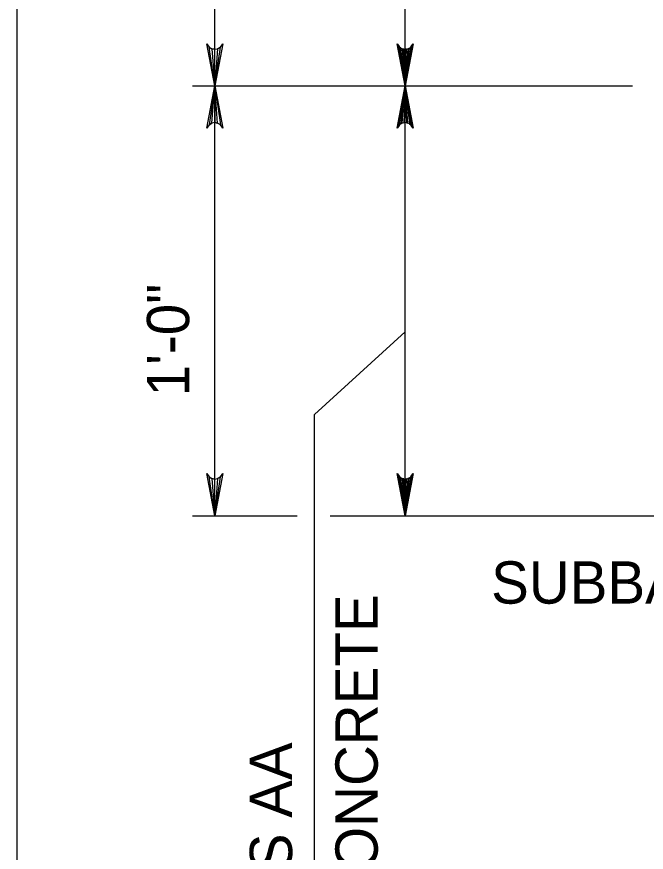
# Model space of a CAD drawing. Extents: x 638079 to 640019, y 297691 to 298879.
# Drawn here: x 639154 to 639198.7, y 298482.1 to 298541.4 of the extents above; entities that cross this region are included whole.
import ezdxf

# ---------------------------------------------------------------- set-up
doc = ezdxf.new("R2010")
doc.units = 0
doc.layers.add('1', color=7, linetype='Continuous')

msp = doc.modelspace()

# ---------------------------------------------------------------- linework, layer by layer
at = {"layer": '1'}
for p, q in [((639168.08, 298506.002), (639168.08, 298577.121)), ((639181.579, 298536.482), (639181.579, 298577.121)), ((639166.511, 298536.482), (639197.7, 298536.482)), ((639181.579, 298506.002), (639181.579, 298536.482)), ((639175.158, 298513.187), (639181.579, 298519.046)), ((639175.158, 298461.31), (639175.158, 298513.187)), ((639166.511, 298506.002), (639173.924, 298506.002)), ((639176.255, 298506.002), (639210.796, 298506.002))]:
    msp.add_line(p, q, dxfattribs=at)
for points in [[(639940.033, 298300.226), (639940.033, 298864.226), (639154.033, 298864.226), (639154.033, 298300.226), (639940.033, 298300.226), (639940.033, 298326.585), (639740.033, 298326.585), (639740.033, 298391.263), (639940.033, 298391.263), (639940.033, 298420.226), (639740.033, 298420.226), (639740.033, 298300.226), (639818.835, 298300.226), (639818.835, 298326.585), (639818.835, 298300.226), (639895.835, 298300.226), (639895.835, 298326.585), (639895.835, 298314.269), (639940.033, 298314.269)], [(639168.08, 298536.482), (639167.521, 298539.465), (639167.68, 298539.235), (639167.88, 298539.117), (639168.08, 298539.082), (639168.28, 298539.117), (639168.48, 298539.235), (639168.64, 298539.465), (639168.08, 298536.482), (639168.48, 298539.235), (639168.28, 298539.117), (639168.08, 298536.482), (639168.08, 298539.082), (639167.88, 298539.117), (639168.08, 298536.482), (639167.68, 298539.235)], [(639181.579, 298536.482), (639181.02, 298539.465), (639181.1, 298539.35), (639181.179, 298539.235), (639181.279, 298539.176), (639181.379, 298539.117), (639181.479, 298539.099), (639181.579, 298539.082), (639181.679, 298539.099), (639181.779, 298539.117), (639181.879, 298539.176), (639181.979, 298539.235), (639182.059, 298539.35), (639182.139, 298539.465), (639181.579, 298536.482), (639182.059, 298539.35), (639181.979, 298539.235), (639181.579, 298536.482), (639181.879, 298539.176), (639181.779, 298539.117), (639181.579, 298536.482), (639181.679, 298539.099), (639181.579, 298539.082), (639181.579, 298536.482), (639181.479, 298539.099), (639181.379, 298539.117), (639181.579, 298536.482), (639181.279, 298539.176), (639181.179, 298539.235), (639181.579, 298536.482), (639181.1, 298539.35)], [(639168.08, 298536.482), (639168.64, 298533.5), (639168.48, 298533.73), (639168.28, 298533.848), (639168.08, 298533.882), (639167.88, 298533.848), (639167.68, 298533.73), (639167.521, 298533.5), (639168.08, 298536.482), (639167.68, 298533.73), (639167.88, 298533.848), (639168.08, 298536.482), (639168.08, 298533.882), (639168.28, 298533.848), (639168.08, 298536.482), (639168.48, 298533.73)], [(639181.579, 298536.482), (639182.139, 298533.5), (639182.059, 298533.615), (639181.979, 298533.73), (639181.879, 298533.789), (639181.779, 298533.848), (639181.679, 298533.865), (639181.579, 298533.882), (639181.479, 298533.865), (639181.379, 298533.848), (639181.279, 298533.789), (639181.179, 298533.73), (639181.1, 298533.615), (639181.02, 298533.5), (639181.579, 298536.482), (639181.1, 298533.615), (639181.179, 298533.73), (639181.579, 298536.482), (639181.279, 298533.789), (639181.379, 298533.848), (639181.579, 298536.482), (639181.479, 298533.865), (639181.579, 298533.882), (639181.579, 298536.482), (639181.679, 298533.865), (639181.779, 298533.848), (639181.579, 298536.482), (639181.879, 298533.789), (639181.979, 298533.73), (639181.579, 298536.482), (639182.059, 298533.615)], [(639168.08, 298506.002), (639167.521, 298508.985), (639167.68, 298508.755), (639167.88, 298508.637), (639168.08, 298508.602), (639168.28, 298508.637), (639168.48, 298508.755), (639168.64, 298508.985), (639168.08, 298506.002), (639168.48, 298508.755), (639168.28, 298508.637), (639168.08, 298506.002), (639168.08, 298508.602), (639167.88, 298508.637), (639168.08, 298506.002), (639167.68, 298508.755)], [(639168.08, 298506.002), (639167.521, 298508.985), (639167.68, 298508.755), (639167.88, 298508.637), (639168.08, 298508.602), (639168.28, 298508.637), (639168.48, 298508.755), (639168.64, 298508.985), (639168.08, 298506.002), (639168.48, 298508.755), (639168.28, 298508.637), (639168.08, 298506.002), (639168.08, 298508.602), (639167.88, 298508.637), (639168.08, 298506.002), (639167.68, 298508.755)], [(639181.579, 298506.002), (639181.02, 298508.985), (639181.1, 298508.87), (639181.179, 298508.755), (639181.279, 298508.696), (639181.379, 298508.637), (639181.479, 298508.619), (639181.579, 298508.602), (639181.679, 298508.619), (639181.779, 298508.637), (639181.879, 298508.696), (639181.979, 298508.755), (639182.059, 298508.87), (639182.139, 298508.985), (639181.579, 298506.002), (639182.059, 298508.87), (639181.979, 298508.755), (639181.579, 298506.002), (639181.879, 298508.696), (639181.779, 298508.637), (639181.579, 298506.002), (639181.679, 298508.619), (639181.579, 298508.602), (639181.579, 298506.002), (639181.479, 298508.619), (639181.379, 298508.637), (639181.579, 298506.002), (639181.279, 298508.696), (639181.179, 298508.755), (639181.579, 298506.002), (639181.1, 298508.87)]]:
    msp.add_lwpolyline(points, dxfattribs=at)

# ---------------------------------------------------------------- texts
for s, p in [('1\'-0"', (639166.265, 298514.468)), ('CEMENT CONCRETE', (639179.634, 298459.863)), ('CLASS AA', (639173.562, 298470.304))]:
    msp.add_text(s, height=3, rotation=90, dxfattribs=at).set_placement(p)
msp.add_text('SUBBASE', height=3, dxfattribs=at).set_placement((639187.675, 298499.766))

doc.saveas('drawing.dxf')
